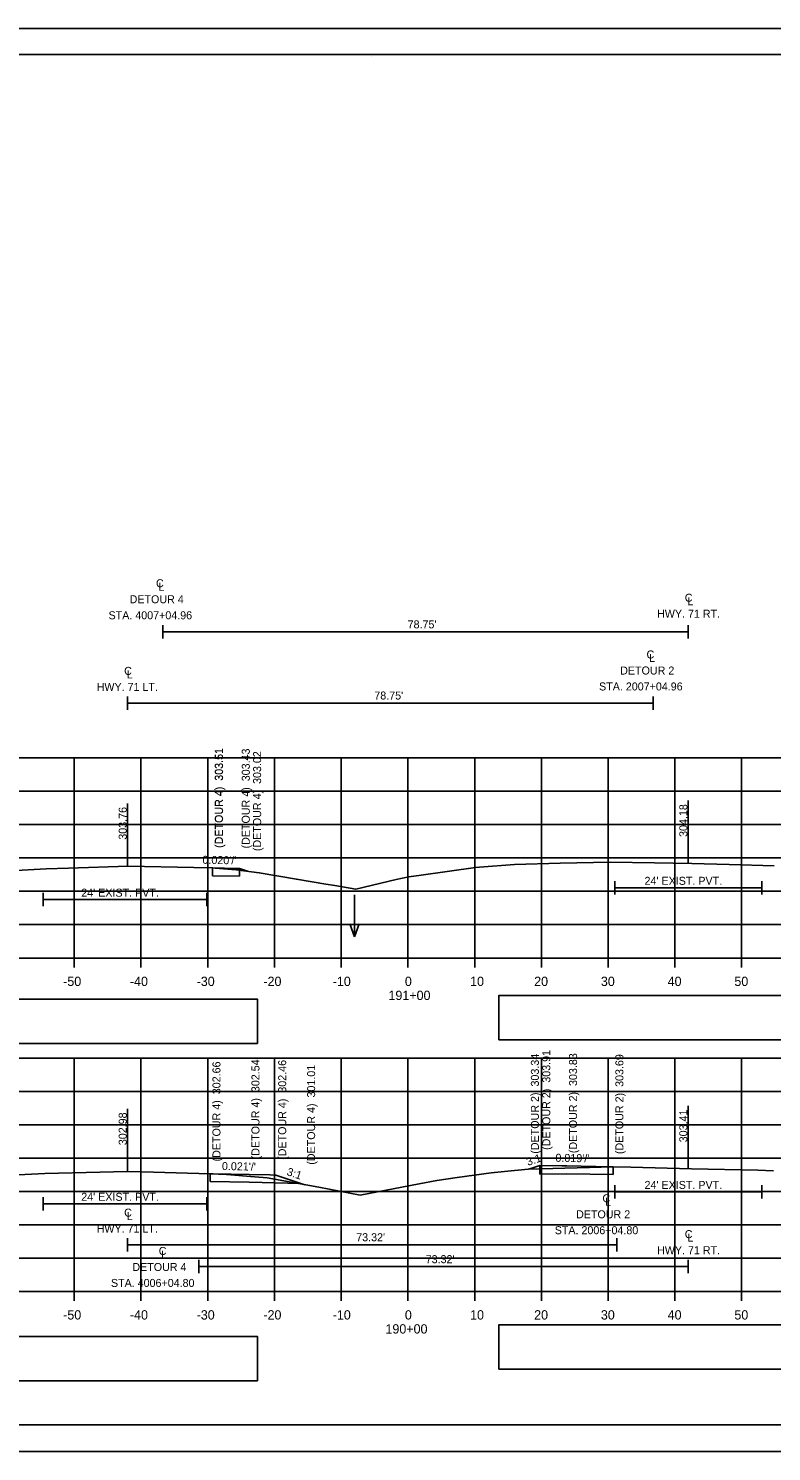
# Model space of a CAD drawing. Extents: x 285 to 4233, y -659 to 3710.
# Drawn here: x 1166.8 to 1278.2, y 2945.6 to 3159 of the extents above; entities that cross this region are included whole.
import ezdxf

# ---------------------------------------------------------------- set-up
doc = ezdxf.new("R2010")
doc.units = 0
for name, color, linetype in [('R_Alt Surface', 7, 'Continuous'), ('R_Axis', 7, 'Continuous'), ('R_Axis Annot', 7, 'Continuous'), ('R_Border', 7, 'Continuous'), ('R_Detour', 7, 'Continuous'), ('R_Detour Annot', 7, 'Continuous'), ('R_Exist Surface', 7, 'Continuous'), ('R_Grid', 7, 'Continuous'), ('R_No Plot', 7, 'Continuous'), ('R_Water', 7, 'Continuous'), ('R_Water Annot', 7, 'Continuous'), ('R_Xsect Elev', 7, 'Continuous')]:
    doc.layers.add(name, color=color, linetype=linetype)

msp = doc.modelspace()

# ---------------------------------------------------------------- linework, layer by layer
at = {"layer": 'R_Alt Surface'}
for points in [[(1186.93, 3069.51), (1186.93, 3067.51)], [(1265.68, 3068.51), (1186.93, 3068.51)], [(1265.68, 3069.51), (1265.68, 3067.51)], [(1181.68, 3058.83), (1181.68, 3056.83)], [(1181.68, 3057.83), (1260.43, 3057.83)], [(1260.43, 3058.83), (1260.43, 3056.83)], [(1254.68, 3031.14), (1254.68, 3029.14)], [(1254.68, 3030.14), (1276.68, 3030.14)], [(1276.68, 3031.14), (1276.68, 3029.14)], [(1169.03, 3029.36), (1169.03, 3027.36)], [(1169.03, 3028.36), (1193.53, 3028.36)], [(1193.53, 3029.36), (1193.53, 3027.36)], [(1254.68, 2985.54), (1254.68, 2983.54)], [(1276.68, 2985.54), (1276.68, 2983.54)], [(1169.03, 2983.77), (1169.03, 2981.77)], [(1169.03, 2982.77), (1193.53, 2982.77)], [(1193.53, 2983.77), (1193.53, 2981.77)], [(1254.68, 2984.54), (1276.68, 2984.54)], [(1181.68, 2977.62), (1181.68, 2975.62)], [(1181.68, 2976.62), (1255, 2976.62)], [(1255, 2977.62), (1255, 2975.62)], [(1192.36, 2974.34), (1192.36, 2972.34)], [(1265.68, 2974.34), (1265.68, 2972.34)], [(1265.68, 2973.34), (1192.36, 2973.34)]]:
    msp.add_lwpolyline(points, dxfattribs=at)
at = {"layer": 'R_Axis'}
for p, q in [((1073.68, 3019.61), (1373.68, 3019.61)), ((1173.68, 3018.21), (1173.68, 3019.61)), ((1183.68, 3018.21), (1183.68, 3019.61)), ((1193.68, 3018.21), (1193.68, 3019.61)), ((1203.68, 3018.21), (1203.68, 3019.61)), ((1213.68, 3018.21), (1213.68, 3019.61)), ((1223.68, 3018.21), (1223.68, 3019.61)), ((1233.68, 3018.21), (1233.68, 3019.61)), ((1243.68, 3018.21), (1243.68, 3019.61)), ((1253.68, 3018.21), (1253.68, 3019.61)), ((1263.68, 3018.21), (1263.68, 3019.61)), ((1273.68, 3018.21), (1273.68, 3019.61)), ((1073.68, 2969.61), (1373.68, 2969.61)), ((1173.68, 2968.21), (1173.68, 2969.61)), ((1183.68, 2968.21), (1183.68, 2969.61)), ((1193.68, 2968.21), (1193.68, 2969.61)), ((1203.68, 2968.21), (1203.68, 2969.61)), ((1213.68, 2968.21), (1213.68, 2969.61)), ((1223.68, 2968.21), (1223.68, 2969.61)), ((1233.68, 2968.21), (1233.68, 2969.61)), ((1243.68, 2968.21), (1243.68, 2969.61)), ((1253.68, 2968.21), (1253.68, 2969.61)), ((1263.68, 2968.21), (1263.68, 2969.61)), ((1273.68, 2968.21), (1273.68, 2969.61))]:
    msp.add_line(p, q, dxfattribs=at)
at = {"layer": 'R_Axis Annot'}
for points in [[(1073.44, 3006.8), (1201.13, 3006.8), (1201.13, 3013.45), (1073.44, 3013.45)], [(1237.31, 3007.35), (1377.31, 3007.35), (1377.31, 3014), (1237.31, 3014)], [(1237.31, 2957.98), (1377.31, 2957.98), (1377.31, 2964.63), (1237.31, 2964.63)], [(1073.44, 2956.23), (1201.13, 2956.23), (1201.13, 2962.88), (1073.44, 2962.88)]]:
    msp.add_lwpolyline(points, close=True, dxfattribs=at)
at = {"layer": 'R_Border'}
for p, q in [((1065.68, 3155.07), (1381.86, 3155.07)), ((1218.2, 3154.81), (1218.2, 3154.81)), ((1218.2, 3154.81), (1218.2, 3154.81)), ((1381.86, 2949.61), (1065.68, 2949.61))]:
    msp.add_line(p, q, dxfattribs=at)
at = {"layer": 'R_Detour'}
for p, q in [((1194.38, 3033.11), (1194.38, 3031.94)), ((1198.43, 3033.03), (1198.43, 3031.86)), ((1194.04, 2987.27), (1194.04, 2986.1)), ((1243.46, 2988.51), (1243.46, 2987.19)), ((1254.41, 2988.3), (1254.41, 2987.13))]:
    msp.add_line(p, q, dxfattribs=at)
for points in [[(1194.38, 3033.11), (1194.39, 3033.11), (1194.43, 3033.11), (1197.95, 3033.04), (1198.43, 3033.03), (1199.47, 3032.68), (1199.64, 3032.63)], [(1194.38, 3031.94), (1194.43, 3031.94), (1198.43, 3031.86)], [(1194.04, 2987.27), (1194.52, 2987.26), (1199.88, 2987.15), (1203, 2987.08), (1203.89, 2987.06), (1206.87, 2986.07), (1208.22, 2985.62)], [(1241.75, 2987.94), (1242.24, 2988.11), (1243.46, 2988.51), (1246.75, 2988.45), (1247.47, 2988.43), (1253.97, 2988.31), (1254.41, 2988.3)], [(1243.46, 2987.19), (1247.47, 2987.27), (1254.41, 2987.13)], [(1194.04, 2986.1), (1194.04, 2986.1), (1199.88, 2985.98), (1207.63, 2985.82)]]:
    msp.add_lwpolyline(points, dxfattribs=at)
at = {"layer": 'R_Exist Surface'}
for points in [[(1161.33, 3032.52), (1169.46, 3032.99), (1172.8, 3033.09), (1181.76, 3033.37), (1191.61, 3033.17), (1194.38, 3033.11), (1194.78, 3033.08), (1197.92, 3032.84), (1199.07, 3032.7), (1201.41, 3032.4), (1206.98, 3031.41), (1211.37, 3030.69), (1212.71, 3030.5), (1215.87, 3029.91), (1221.92, 3031.38), (1223.8, 3031.8), (1225.66, 3032.05), (1233.82, 3033.18), (1234.39, 3033.22), (1239.67, 3033.64), (1246.49, 3033.82), (1254, 3034), (1260.6, 3033.88), (1266.24, 3033.77), (1271.81, 3033.62), (1278.55, 3033.44)], [(1163.3, 2986.98), (1169.25, 2987.3), (1177.52, 2987.49), (1181.61, 2987.58), (1185.54, 2987.49), (1194.04, 2987.27), (1196.47, 2987.13), (1197.75, 2987.05), (1199.49, 2986.91), (1202.61, 2986.64), (1210.33, 2985.24), (1216.52, 2984.06), (1225.36, 2985.74), (1228.02, 2986.27), (1231.06, 2986.69), (1236.16, 2987.38), (1238.13, 2987.58), (1241.69, 2987.95), (1250.88, 2988.21), (1254.41, 2988.3), (1257.06, 2988.24), (1266.18, 2988), (1276.09, 2987.78), (1278.46, 2987.72)]]:
    msp.add_lwpolyline(points, dxfattribs=at)
at = {"layer": 'R_Grid'}
for p, q in [((1073.68, 3049.61), (1373.68, 3049.61)), ((1173.68, 3019.61), (1173.68, 3049.61)), ((1183.68, 3019.61), (1183.68, 3049.61)), ((1193.68, 3019.61), (1193.68, 3049.61)), ((1203.68, 3019.61), (1203.68, 3049.61)), ((1213.68, 3019.61), (1213.68, 3049.61)), ((1223.68, 3019.61), (1223.68, 3049.61)), ((1233.68, 3019.61), (1233.68, 3049.61)), ((1243.68, 3019.61), (1243.68, 3049.61)), ((1253.68, 3019.61), (1253.68, 3049.61)), ((1263.68, 3019.61), (1263.68, 3049.61)), ((1273.68, 3019.61), (1273.68, 3049.61)), ((1073.68, 3044.61), (1373.68, 3044.61)), ((1073.68, 3039.61), (1373.68, 3039.61)), ((1073.68, 3034.61), (1373.68, 3034.61)), ((1073.68, 3029.61), (1373.68, 3029.61)), ((1073.68, 3024.61), (1373.68, 3024.61)), ((1073.68, 3019.61), (1373.68, 3019.61)), ((1073.68, 3004.61), (1373.68, 3004.61)), ((1173.68, 2969.61), (1173.68, 3004.61)), ((1183.68, 2969.61), (1183.68, 3004.61)), ((1193.68, 2969.61), (1193.68, 3004.61)), ((1203.68, 2969.61), (1203.68, 3004.61)), ((1213.68, 2969.61), (1213.68, 3004.61)), ((1223.68, 2969.61), (1223.68, 3004.61)), ((1233.68, 2969.61), (1233.68, 3004.61)), ((1243.68, 2969.61), (1243.68, 3004.61)), ((1253.68, 2969.61), (1253.68, 3004.61)), ((1263.68, 2969.61), (1263.68, 3004.61)), ((1273.68, 2969.61), (1273.68, 3004.61)), ((1073.68, 2999.61), (1373.68, 2999.61)), ((1073.68, 2994.61), (1373.68, 2994.61)), ((1073.68, 2989.61), (1373.68, 2989.61)), ((1073.68, 2984.61), (1373.68, 2984.61)), ((1073.68, 2979.61), (1373.68, 2979.61)), ((1073.68, 2974.61), (1373.68, 2974.61)), ((1073.68, 2969.61), (1373.68, 2969.61))]:
    msp.add_line(p, q, dxfattribs=at)
at = {"layer": 'R_No Plot'}
for p, q in [((1053.28, 3158.96), (1386.61, 3158.96)), ((1053.28, 2945.63), (1386.61, 2945.63))]:
    msp.add_line(p, q, dxfattribs=at)
for points in [[(1053.27, 3158.96), (1386.61, 3158.96), (1386.61, 2945.62), (1053.27, 2945.62)], [(1299.6, 3155.07), (1319.22, 3155.07), (1319.22, 3145.19), (1335.33, 3145.19), (1358.53, 3145.19), (1358.65, 3117.03), (1381.86, 3117.03), (1381.86, 2949.61), (1065.68, 2949.61), (1065.68, 3155.07)]]:
    msp.add_lwpolyline(points, close=True, dxfattribs=at)
at = {"layer": 'R_Water Annot'}
for p, q in [((1215.68, 3029.09), (1215.68, 3022.8)), ((1215.68, 3022.8), (1214.98, 3024.73)), ((1215.68, 3022.8), (1216.38, 3024.73))]:
    msp.add_line(p, q, dxfattribs=at)
at = {"layer": 'R_Xsect Elev'}
for p, q in [((1181.68, 3033.36), (1181.68, 3042.79)), ((1265.68, 3033.78), (1265.68, 3043.2)), ((1265.68, 2988.01), (1265.68, 2997.43)), ((1181.68, 2987.58), (1181.68, 2997))]:
    msp.add_line(p, q, dxfattribs=at)

# ---------------------------------------------------------------- texts
at = {"layer": 'R_Alt Surface'}
for s, height, p in [('C', 1.2, (1185.93, 3075.19)), ('L', 1.2, (1186.31, 3074.66)), ('C', 1.2, (1265.16, 3073.02)), ('DETOUR 4', 1.199, (1181.98, 3072.79)), ('L', 1.2, (1265.55, 3072.49)), ('STA. 4007+04.96', 1.1985, (1178.82, 3070.39)), ('HWY. 71 RT.', 1.1985, (1261.01, 3070.62)), ('C', 1.2, (1259.43, 3064.51)), ('L', 1.2, (1259.81, 3063.98)), ('C', 1.2, (1181.16, 3062.05)), ('L', 1.2, (1181.54, 3061.52)), ('DETOUR 2', 1.199, (1255.48, 3062.11)), ('HWY. 71 LT.', 1.1985, (1177.04, 3059.65)), ('STA. 2007+04.96', 1.1985, (1252.32, 3059.72)), ('C', 1.2, (1252.82, 2982.99)), ('L', 1.2, (1253.2, 2982.46)), ('C', 1.2, (1181.16, 2980.84)), ('L', 1.2, (1181.54, 2980.31)), ('DETOUR 2', 1.199, (1248.87, 2980.59)), ('HWY. 71 LT.', 1.1985, (1177.04, 2978.44)), ('STA. 2006+04.80', 1.1985, (1245.67, 2978.2)), ('C', 1.2, (1265.16, 2977.61)), ('L', 1.2, (1265.55, 2977.08)), ('C', 1.2, (1186.34, 2975.09)), ('HWY. 71 RT.', 1.1985, (1261.01, 2975.21)), ('L', 1.2, (1186.72, 2974.56)), ('DETOUR 4', 1.199, (1182.39, 2972.69)), ('STA. 4006+04.80', 1.1985, (1179.18, 2970.3))]:
    msp.add_text(s, height=height, dxfattribs=at).set_placement(p)
at = {"layer": 'R_Axis Annot'}
for s, p in [('-50', (1172.02, 3015.41)), ('-40', (1182.02, 3015.41)), ('-30', (1192.02, 3015.41)), ('-20', (1202.02, 3015.41)), ('-10', (1212.41, 3015.41)), ('0', (1223.22, 3015.41)), ('10', (1232.99, 3015.41)), ('20', (1242.59, 3015.41)), ('30', (1252.59, 3015.41)), ('40', (1262.59, 3015.41)), ('50', (1272.59, 3015.41)), ('191+00', (1220.76, 3013.31)), ('-50', (1172.02, 2965.41)), ('-40', (1182.02, 2965.41)), ('-30', (1192.02, 2965.41)), ('-20', (1202.02, 2965.41)), ('-10', (1212.41, 2965.41)), ('0', (1223.22, 2965.41)), ('10', (1232.99, 2965.41)), ('20', (1242.59, 2965.41)), ('30', (1252.59, 2965.41)), ('40', (1262.59, 2965.41)), ('50', (1272.59, 2965.41)), ('190+00', (1220.31, 2963.31))]:
    msp.add_text(s, height=1.4, dxfattribs=at).set_placement(p)
at = {"layer": 'R_Detour Annot'}
for s, rotation, p in [('(DETOUR 4)  303.51', 90, (1195.93, 3036.11)), ('(DETOUR 4)  303.51', 90, (1195.98, 3036.11)), ('(DETOUR 4)  303.43', 90, (1199.98, 3036.03)), ('(DETOUR 4)  303.02', 90, (1201.68, 3035.63)), ("0.020'/'", 358.8531, (1192.88, 3033.74)), ('(DETOUR 4)  302.66', 90, (1195.59, 2989.11)), ('(DETOUR 4)  302.54', 90, (1201.43, 2989.43)), ('(DETOUR 4)  302.46', 90, (1205.44, 2989.35)), ('(DETOUR 2)  303.34', 90, (1243.3, 2990.27)), ('(DETOUR 2)  303.91', 90, (1245.01, 2990.84)), ('(DETOUR 2)  303.83', 90, (1249.02, 2990.35)), ('(DETOUR 2)  303.69', 90, (1255.96, 2990.21)), ('(DETOUR 4)  301.01', 90, (1209.77, 2988.62)), ("0.021'/'", 358.8005, (1195.8, 2987.83)), ('3:1', 18.4081, (1241.66, 2988.44)), ("0.019'/'", 358.8914, (1245.77, 2989.07)), ('3:1', 341.57, (1205.43, 2987.08))]:
    msp.add_text(s, height=1.2, rotation=rotation, dxfattribs=at).set_placement(p)
at = {"layer": 'R_Water'}
for s, p in [("78.75'", (1223.63, 3069.03)), ("78.75'", (1218.64, 3058.36)), ("24' EXIST. PVT.", (1259.13, 3030.58)), ("24' EXIST. PVT.", (1174.73, 3028.8)), ("24' EXIST. PVT.", (1259.13, 2984.99)), ("24' EXIST. PVT.", (1174.73, 2983.21)), ("73.32'", (1215.93, 2977.15)), ("73.32'", (1226.34, 2973.86))]:
    msp.add_text(s, height=1.2, dxfattribs=at).set_placement(p)
at = {"layer": 'R_Xsect Elev'}
for s, p in [('304.18', (1265.54, 3037.76)), ('303.76', (1181.54, 3037.34)), ('302.98', (1181.54, 2991.55)), ('303.41', (1265.54, 2991.98))]:
    msp.add_text(s, height=1.2, rotation=90, dxfattribs=at).set_placement(p)

doc.saveas('drawing.dxf')
